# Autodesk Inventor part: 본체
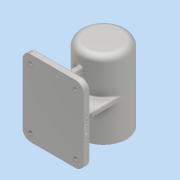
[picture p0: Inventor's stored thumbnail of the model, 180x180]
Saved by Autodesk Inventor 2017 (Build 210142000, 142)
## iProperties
Part Number: 본체
Material: 알루미늄 6061
Document SubType Name: Modeling
Designer: mrc
Density: 2.7 g/cm^3
Appearance: 알루미늄 - 평지
Mass: 1026.24 g
Surface Area: 757.016 cm^2
Volume: 380.088 cm^3
Author: mrc
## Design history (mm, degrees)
sketch "스케치1"
  geometry: L1 (0, 56)-(0, -56); L2 (0, 56)-(34, 56); L3 (34, 56)-(34, -56); L4 (34, -56)-(0, -56); L5 (0, 50)-(10.5, 50); L6 (10.5, 50)-(10.5, 47); L7 (10.5, 47)-(16, 47); L8 (16, 47)-(16, 43); L9 (16, 43)-(17.5, 43); L10 (17.5, 43)-(17.5, 25); L11 (17.5, 25)-(21, 25); L12 (21, 25)-(21, 13); L13 (21, 13)-(24, 13); L14 (24, 13)-(24, -41); L15 (24, -41)-(21, -41); L16 (21, -41)-(21, -56); 2 further points
  constraints: 32 end point, 13 perpendicular, 2 horizontal, 2 point on line, 1 coincident, 1 midpoint, 1 vertical
  dimensions: "d0" = 112 distance of L1.start L1.end; "d1" = 21 diameter of L6 L1; "d2" = 32 diameter of L8 L1; "d3" = 35 diameter of L10 L1; "d4" = 68 diameter of L3 L1; "d5" = 48 diameter of L14 L1; "d6" = 42 diameter of L12 L1; "d7" = 42 diameter of L16 L1; "d8" = 15 distance between parallel lines of L4 L15; "d9" = 54 distance between parallel lines of L13 L15; "d10" = 12 distance between parallel lines of L11 L13; "d11" = 18 distance between parallel lines of L9 L11; "d12" = 4 distance between parallel lines of L7 L9; "d13" = 3 distance between parallel lines of L5 L7
revolve "회전1" sketch "스케치1" stored, may be unused: angle "d14" = 90 deg
fillet "모깎기1" dims "d15" = 3
fillet "모깎기2" dims "d16" = 0.3
fillet "모깎기3" dims "d17" = 3
chamfer "모따기1" distance "d18" = 1; stored, may be unused: second distance "d19" = 2, angle "d20" = 45 deg
sketch "스케치2"
  geometry: 2 further points
  constraints: 1 vertical alignment
  dimensions: "d21" = 26 distance of point (0, 0) point (0, 26)
hole "구멍1" sketch "스케치2" at (0, 26) diameter "d22" = 3.242; stored, may be unused: countersink angle "d26" = 90 deg, drill point angle "d28" = 118 deg; dims "d23" = 8, "d24" = 4, "d25" = 2, "d27" = 11
fillet "모깎기4" dims "d32" = 10
sketch "스케치3"
  geometry: L1 (-64, 56)-(-74, 56); L2 (-74, 56)-(-74, -56); L3 (-74, -56)-(-64, -56); L4 (-64, -56)-(-64, 56); 2 further points
  constraints: 8 end point, 2 parallel, 1 horizontal, 1 horizontal alignment, 1 midpoint, 1 perpendicular
  dimensions: "d33" = 10 distance of L3.end L2.end; "d34" = 112 distance of L2.end L1.end; "d37" = 74 distance from line of L2 point (0, 0)
extrude "돌출1" join sketch "스케치3" stored distance "d35" = 90; taper "d36" = 0 deg
fillet "모깎기5" dims "d38" = 12
sketch "스케치4"
  geometry: L1 (29, 18)-(37, 18); L2 (37, 18)-(37, 94); L3 (37, 94)-(29, 94); L4 (29, 94)-(29, 18); L5 (29, 18)-(37, 94); L6 (37, 18)-(29, 94); L7 (0, 0)-(66, 0) reference; L8 (-1, 52)-(67, 52); L9 (67, 52)-(67, 60); L10 (67, 60)-(-1, 60); L11 (-1, 60)-(-1, 52); L12 (-1, 52)-(67, 60); L13 (67, 52)-(-1, 60); 1 further point
  constraints: 24 end point, 4 midpoint, 4 parallel, 2 horizontal, 2 perpendicular
  dimensions: "d39" = 8 distance of L3.end L2.end; "d40" = 18 distance between parallel lines of L1 L7; "d41" = 8 distance of L9.end L8.end; "d42" = 68 distance of L9.end L10.end
extrude "돌출2" join sketch "스케치4" stored distance "d43" = 90; taper "d44" = 0 deg
hole "구멍2" diameter "d47" = 5.5; stored, may be unused: countersink angle "d51" = 90 deg, drill point angle "d53" = 0 deg; dims "d45" = 10, "d46" = 10, "d48" = 8, "d49" = 9.5, "d50" = 5.4, "d52" = 11
fillet "모깎기6" dims "d60" = 3
fillet "모깎기7" dims "d61" = 3
fillet "모깎기8" dims "d62" = 3
fillet "모깎기9" dims "d63" = 3
sketch "스케치7"
  geometry: L1 (-44, -74)-(44, -74) reference; L2 (56, -74)-(56, -67) reference; 2 further points
  constraints: 1 other
  dimensions: "d64" = 3 distance from line of L1 point (0, -71); "d67" = 56 distance from line of L2 point (0, -71)
feature "엠보싱1" sketch "스케치7" dims "d0" = 112, "d1" = 21, "d2" = 32, "d3" = 35, "d4" = 68, "d5" = 48, "d6" = 42, "d7" = 42, "d8" = 15, "d9" = 54, "d10" = 12, "d11" = 18, "d12" = 4, "d13" = 3, "d65" = 0.5, "d66" = 0
node "솔리드1"
pattern_circular "원형 패턴1" dims angle "d30" = 360 deg
pattern_linear "직사각형 패턴1" dims "d56" = 88, "d59" = 66
